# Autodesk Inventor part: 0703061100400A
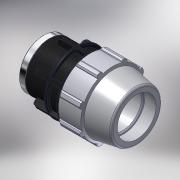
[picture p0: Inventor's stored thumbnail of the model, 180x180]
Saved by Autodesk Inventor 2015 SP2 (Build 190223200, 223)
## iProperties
Created: 2017-02
Part Number: 0703061100400A
Material: PVC-Piping
Description: PLASSON FEMALE ADAPTOR 110-4"
Document SubType Name: Modeling
Designer: KIM
Mass: 92.6774 g
Surface Area: 199.44 cm^2
Volume: 66.1981 cm^3
Density: 1.4 g/cm^3
Appearance: PTFE
Author: KIM
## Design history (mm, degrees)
derived "87030.ipt"
feature "Solid1::87030.ipt"
tag "TaggingFeature1"
body "Solid1"
other parameters: "d4" = 38.71429, "d5" = 67.75, "d7" = 181, "d9" = 38.71429, "d11" = 7.74286, "d12" = 144.8, "d13" = 120 deg, "d14" = 143, "d15" = 8 deg, "d16" = 162.9, "d18" = 5.5, "d19" = 35 deg, "d20" = 17.5 deg, "d21" = 168.33, "d23" = 0, "d25" = 360 deg, "d27" = 3.62, "d34" = 9.05, "d35" = 81.3, "d36" = 0, "d42" = 67.75, "d43" = 5.43, "d46" = 3.3, "d49" = 213, "d51" = 271, "d53" = 2.2, "d55" = 360 deg, "d62" = 77, "d63" = 110.072, "d64" = 90.33333, "d65" = 9.05, "d69" = 130.32, "d70" = 4.525, "d71" = 12.6, "d72" = 0.5, "d73" = 1, "E_" = 181, "H_" = 271, "l_" = 213, "Rp_Rc_" = 110.072
